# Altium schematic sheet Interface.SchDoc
size A4
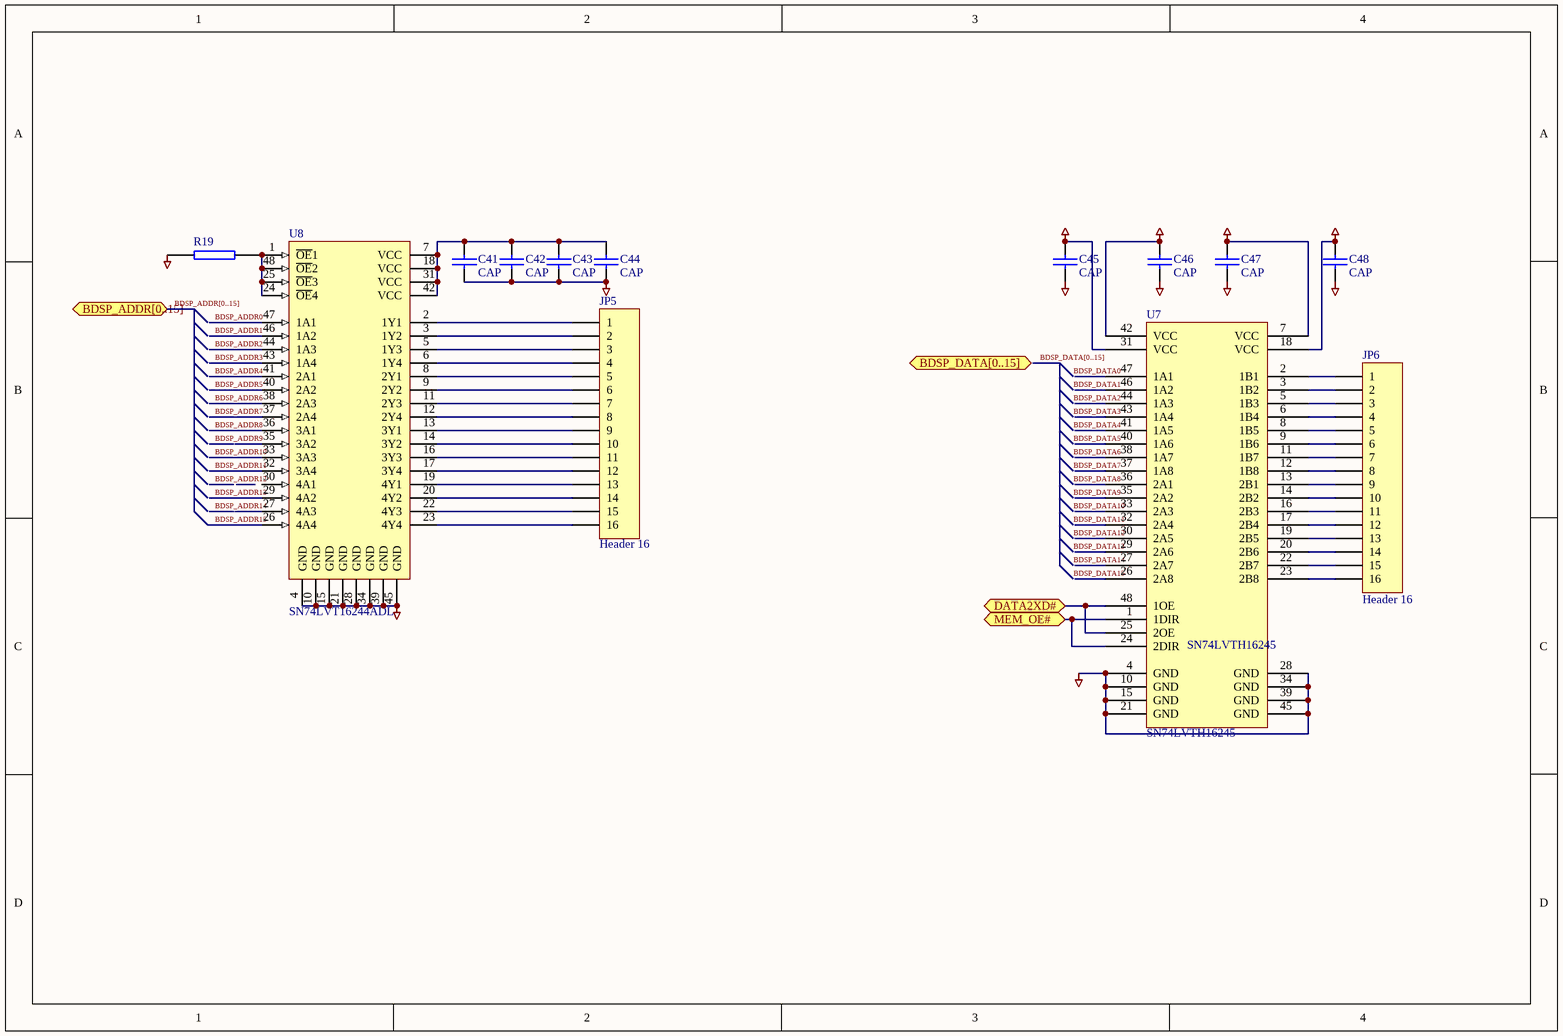
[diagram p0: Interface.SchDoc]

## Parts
C41  CAP  [CC2012-0805]
C42  CAP  [CC2012-0805]
C43  CAP  [CC2012-0805]
C44  CAP  [CC2012-0805]
C45  CAP  [CC2012-0805]
C46  CAP  [CC2012-0805]
C47  CAP  [CC2012-0805]
C48  CAP  [CC2012-0805]
JP5  Header 16  [HDR1X16]
JP6  Header 16  [HDR1X16]
R19  (no value)  [R2012-0805]
U7  SN74LVTH16245  [TSOP48]
U8  SN74LVT16244ADL  [SSO-G48]

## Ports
BDSP_ADDR[0..15], BDSP_DATA[0..15], DATA2XD#, MEM_OE#

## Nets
3.3V: C45.1 C46.1 C47.1 C48.1 U7.7(VCC) U7.18(VCC) U7.31(VCC) U7.42(VCC)
DGND: C41.2 C42.2 C43.2 C44.2 C45.2 C46.2 C47.2 C48.2 R19.2 U7.4(GND) U7.10(GND) U7.15(GND) U7.21(GND) U7.28(GND) U7.34(GND) U7.39(GND) U7.45(GND) U8.4(GND) U8.10(GND) U8.15(GND) U8.21(GND) U8.28(GND) U8.34(GND) U8.39(GND) U8.45(GND)
BDSP_ADDR0: U8.47(1A1)
BDSP_ADDR1: U8.46(1A2)
BDSP_ADDR2: U8.44(1A3)
BDSP_ADDR3: U8.43(1A4)
BDSP_ADDR4: U8.41(2A1)
BDSP_ADDR5: U8.40(2A2)
BDSP_ADDR6: U8.38(2A3)
BDSP_ADDR7: U8.37(2A4)
BDSP_ADDR8: U8.36(3A1)
BDSP_ADDR10: U8.33(3A3)
BDSP_ADDR11: U8.32(3A4)
BDSP_ADDR13: U8.29(4A2)
BDSP_ADDR15: U8.26(4A4)
DATA2XD#: U7.25(2OE) U7.48(1OE) ; port DATA2XD#
MEM_OE#: U7.1(1DIR) U7.24(2DIR) ; port MEM_OE#
NetC41_1: C41.1 C42.1 C43.1 C44.1 U8.7(VCC) U8.18(VCC) U8.31(VCC) U8.42(VCC)
NetJP5_1: JP5.1 U8.2(1Y1)
NetJP5_2: JP5.2 U8.3(1Y2)
NetJP5_3: JP5.3 U8.5(1Y3)
NetJP5_4: JP5.4 U8.6(1Y4)
NetJP5_5: JP5.5 U8.8(2Y1)
NetJP5_6: JP5.6 U8.9(2Y2)
NetJP5_7: JP5.7 U8.11(2Y3)
NetJP5_8: JP5.8 U8.12(2Y4)
NetJP5_9: JP5.9 U8.13(3Y1)
NetJP5_10: JP5.10 U8.14(3Y2)
NetJP5_11: JP5.11 U8.16(3Y3)
NetJP5_12: JP5.12 U8.17(3Y4)
NetJP5_13: JP5.13 U8.19(4Y1)
NetJP5_14: JP5.14 U8.20(4Y2)
NetJP5_15: JP5.15 U8.22(4Y3)
NetJP5_16: JP5.16 U8.23(4Y4)
NetJP6_1: JP6.1 U7.2(1B1)
NetJP6_2: JP6.2 U7.3(1B2)
NetJP6_3: JP6.3 U7.5(1B3)
NetJP6_4: JP6.4 U7.6(1B4)
NetJP6_5: JP6.5 U7.8(1B5)
NetJP6_6: JP6.6 U7.9(1B6)
NetJP6_7: JP6.7 U7.11(1B7)
NetJP6_8: JP6.8 U7.12(1B8)
NetJP6_9: JP6.9 U7.13(2B1)
NetJP6_10: JP6.10 U7.14(2B2)
NetJP6_11: JP6.11 U7.16(2B3)
NetJP6_12: JP6.12 U7.17(2B4)
NetJP6_13: JP6.13 U7.19(2B5)
NetJP6_14: JP6.14 U7.20(2B6)
NetJP6_15: JP6.15 U7.22(2B7)
NetJP6_16: JP6.16 U7.23(2B8)
NetR19_1: R19.1 U8.1(~{OE}1) U8.24(~{OE}4) U8.25(~{OE}3) U8.48(~{OE}2)

Not connected (* = marked no-connect by the designer): U7 26(2A8) 27(2A7) 29(2A6) 30(2A5) 32(2A4) 33(2A3) 35(2A2) 36(2A1) 37(1A8) 38(1A7) 40(1A6) 41(1A5) 43(1A4) 44(1A3) 46(1A2) 47(1A1); U8 27(4A3) 30(4A1) 35(3A2)

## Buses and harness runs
bus BDSP_ADDR[0..15] = port BDSP_ADDR[0..15]
bus BDSP_DATA[0..15]

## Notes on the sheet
- Labels drawn without touching a wire or pin: BDSP_DATA0, BDSP_DATA1, BDSP_DATA2, BDSP_DATA3, BDSP_DATA4, BDSP_DATA5, BDSP_DATA6, BDSP_DATA7, BDSP_DATA8, BDSP_DATA9, BDSP_DATA10, BDSP_DATA11, BDSP_DATA12, BDSP_DATA13, BDSP_DATA14, BDSP_DATA15

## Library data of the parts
C41-C48 = CAP: Capacitor
JP5 JP6 = Header 16: Header, 16-Pin; Manufacturer: Generic Components; Class I: Connector
R19 = RES2
U8 = SN74LVT16244ADL: 3.3-V ABT 16-Bit Buffer/Driver with 3-State Outputs; Manufacturer: Texas Instruments; Package Information: Latest Revision: Jan-1998; Class I: Logic; Class II: Buffer/Line Driver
